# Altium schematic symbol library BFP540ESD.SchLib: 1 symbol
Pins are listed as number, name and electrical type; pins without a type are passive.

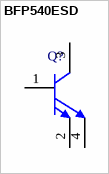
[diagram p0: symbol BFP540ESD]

## BFP540ESD
designator Q?
NPN Silicon RF Transistor, 4.5 V VCEO, 80 mA IC, 21.5 dB Gmax, SOT343, Green; Manufacturer: Infineon; PartNumber: BFP540ESD; Gmax (typ): 21.5 dB; Green: yes; IC (max): 80 mA; NFmin (typ): 0.9 dB; Ptot (max): 250 mW; VCEO (max): 4.5 V
footprint INF-SOT343_V (SOT343, 4-Leads, Body 2x1.25 mm)
pins: 1 B, 2 E, 3 C, 4 E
